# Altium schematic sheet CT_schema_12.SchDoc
size 147 x 119 mm
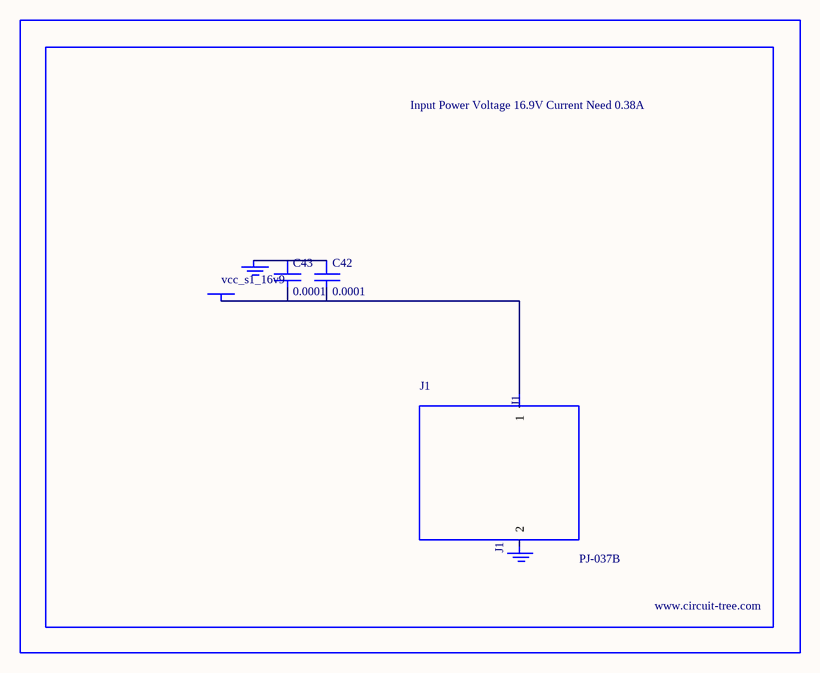
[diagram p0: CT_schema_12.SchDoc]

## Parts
BORDER11  (no value)
C42  0.0001  [EXV-9H]
C43  0.0001  [EXV-9H]
GND_INSTANCE_11_0  (no value)
GND_INSTANCE_11_1  (no value)
J1  PJ-037B  [PJ-037B_PACKAGE]
POWER_INSTANCE_11_0  vcc_s1_16v9

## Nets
NetC42_1: C42.1 C43.1 GND_INSTANCE_11_0.0(GND)
NetC42_2: C42.2 C43.2 J1.1 POWER_INSTANCE_11_0.0(PWR)

Not connected (* = marked no-connect by the designer): GND_INSTANCE_11_1 0(GND); J1 2

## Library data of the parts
BORDER11 = BORDER_PAGE11
C42 C43 = EDK107M035A9HAA
GND_INSTANCE_11_0 GND_INSTANCE_11_1 = GND
POWER_INSTANCE_11_0 = PWR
